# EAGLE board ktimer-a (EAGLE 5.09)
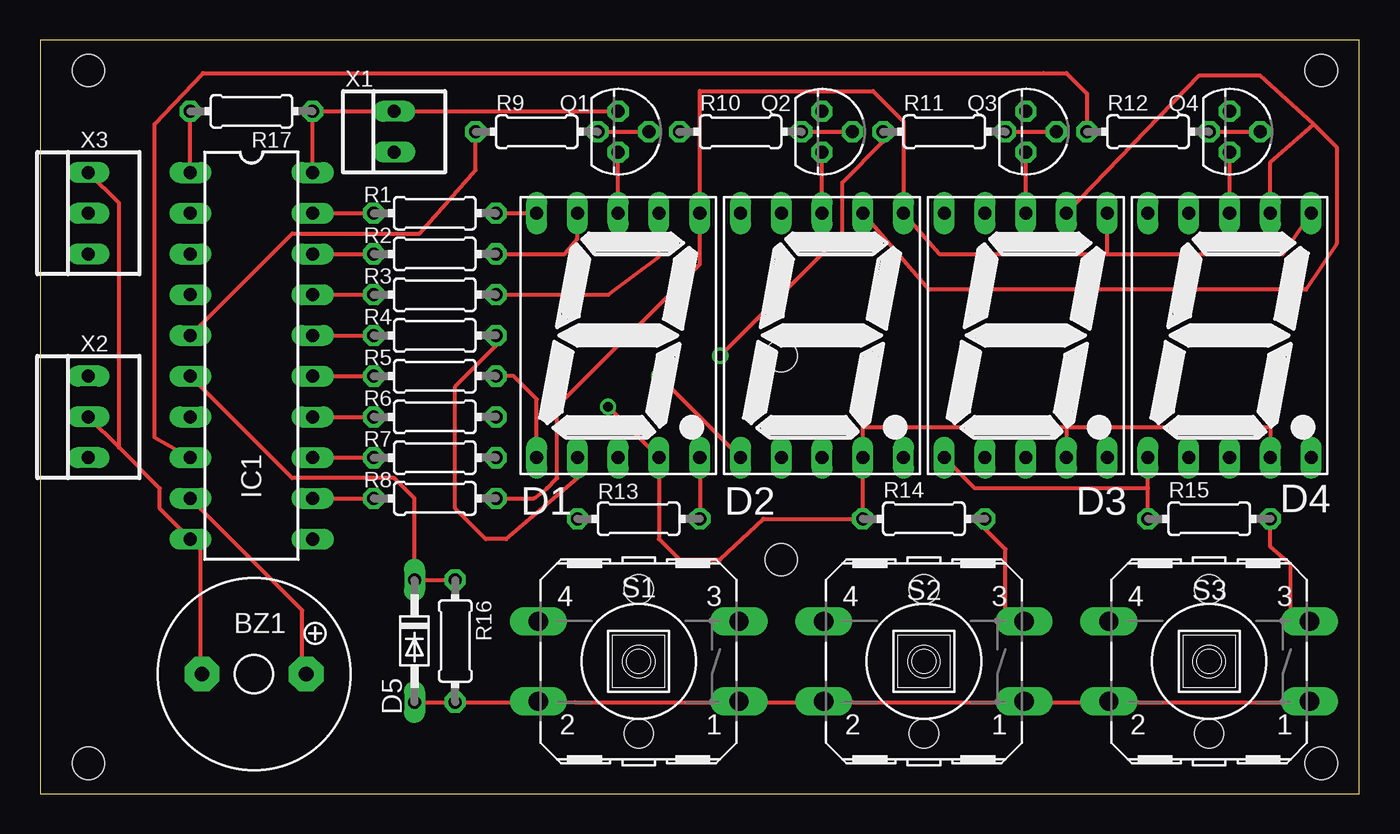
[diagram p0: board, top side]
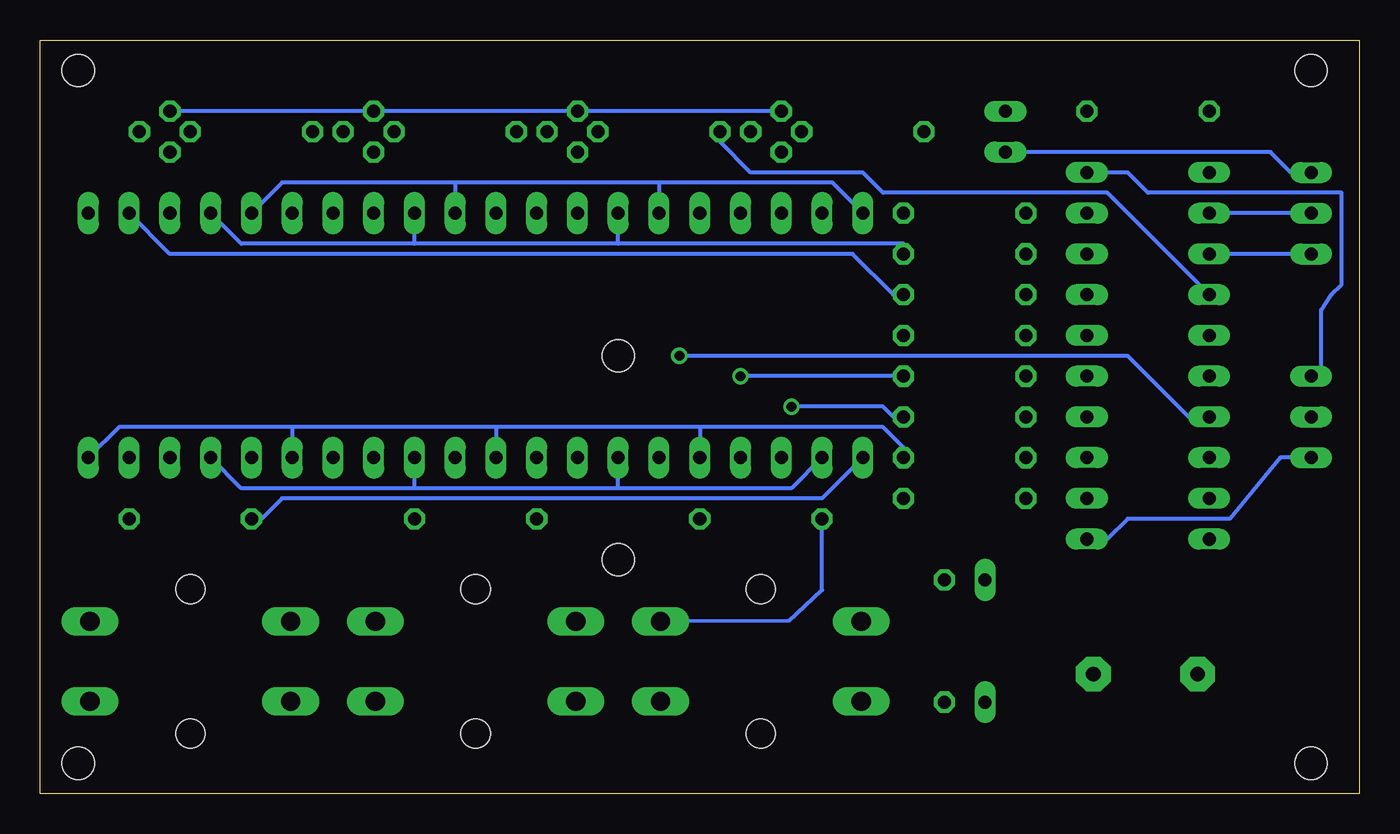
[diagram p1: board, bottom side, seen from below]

Size 82.22 x 46.98 mm. Coordinates in mm from the lower left corner, seen from the top.
Outline: 0,0 82.22,0 82.22,46.98 0,46.98 0,0
Copper layers (1*16): Top 0.035mm / dielectric 1.5mm / Bottom 0.035mm
Design rules "default": minimum track width 10mil, minimum drill 24mil, track to track 8mil, track to pad 8mil, pad to pad 8mil, via to via 8mil, smd to smd 8mil, copper to edge 40mil, drill to drill 8mil, minimum pad ring 10mil, minimum via ring 8mil, stop-mask expansion 4mil, vias tented up to drill 0mil, thermal gap 10mil
Holes 2 mm at 3.01,45.08 3.01,1.9 79.84,1.9 79.84,45.08 46.19,14.6 46.19,27.3

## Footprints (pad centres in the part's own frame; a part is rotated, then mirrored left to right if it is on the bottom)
F/QMBIII = drill 0.914 pad 2.159 octagon: + 3.251,0; - -3.251,0
7SEG-13 = drill 0.813 long: 1 -5.08,-7.62; 2 -2.54,-7.62; 3 0,-7.62; 4 2.54,-7.62; 5 5.08,-7.62; 6 5.08,7.62; 7 2.54,7.62; 8 0,7.62; 9 -2.54,7.62; 10 -5.08,7.62
DO34-7 = drill 0.813 long: A 3.81,0; C -3.81,0
DIL20 = drill 0.813 long: 1 -11.43,-3.81; 2 -8.89,-3.81; 3 -6.35,-3.81; 4 -3.81,-3.81; 5 -1.27,-3.81; 6 1.27,-3.81; 7 3.81,-3.81; 8 6.35,-3.81; 9 8.89,-3.81; 10 11.43,-3.81; 11 11.43,3.81; 12 8.89,3.81; 13 6.35,3.81; 14 3.81,3.81; 15 1.27,3.81; 16 -1.27,3.81; 17 -3.81,3.81; 18 -6.35,3.81; 19 -8.89,3.81; 20 -11.43,3.81
TO92 = drill 0.813 octagon: 1 1.27,0; 2 0,1.905; 3 -1.27,0
0204/7 = drill 0.813 octagon: 1 -3.81,0; 2 3.81,0
B3F-40XX = drill 1.194 long: 1 -6.248,2.489; 2 6.248,2.489; 3 -6.248,-2.489; 4 6.248,-2.489 | hole 1.803: 0,-4.496; 0,4.496
22-23-2021 = drill 0.813 long: 1 -1.27,0; 2 1.27,0
22-23-2031 = drill 0.813 long: 1 -2.54,0; 2 0,0; 3 2.54,0

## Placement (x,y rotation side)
BZ1  KC-1207  [F/QMBIII]  13.33,7.46 0 top
D1  [7SEG-13]  36.03,28.57 0 top
D2  [7SEG-13]  48.73,28.57 0 top
D3  [7SEG-13]  61.43,28.57 0 top
D4  [7SEG-13]  74.13,28.57 0 top
D5  1N4148  [DO34-7]  23.33,9.52 270 top
IC1  ATTINY2313-20PI  [DIL20]  13.17,27.3 270 top
Q1  BC557  [TO92]  36.03,41.27 270 top
Q2  BC557  [TO92]  48.73,41.27 270 top
Q3  BC557  [TO92]  61.43,41.27 270 top
Q4  BC557  [TO92]  74.13,41.27 270 top
R1  220R  [0204/7]  24.6,36.19 0 top
R2  220R  [0204/7]  24.6,33.65 0 top
R3  220R  [0204/7]  24.6,31.11 0 top
R4  220R  [0204/7]  24.6,28.57 0 top
R5  220R  [0204/7]  24.6,26.03 0 top
R6  220R  [0204/7]  24.6,23.49 0 top
R7  220R  [0204/7]  24.6,20.95 0 top
R8  220R  [0204/7]  24.6,18.41 0 top
R9  1k  [0204/7]  30.95,41.27 0 top
R10  1k  [0204/7]  43.65,41.27 0 top
R11  1k  [0204/7]  56.35,41.27 0 top
R12  1k  [0204/7]  69.05,41.27 0 top
R13  2k7  [0204/7]  37.3,17.14 180 top
R14  2k7  [0204/7]  55.08,17.14 0 top
R15  2k7  [0204/7]  72.86,17.14 0 top
R16  100k  [0204/7]  25.87,9.52 270 top
R17  10k  [0204/7]  13.17,42.54 180 top
S1  INC  [B3F-40XX]  37.3,8.25 180 top
S2  DEC  [B3F-40XX]  55.08,8.25 180 top
S3  START  [B3F-40XX]  72.86,8.25 180 top
X1  SUPPLY  [22-23-2021]  22.06,41.27 90 top
X2  XTRNL DEVICE  [22-23-2031]  3.01,23.49 90 top
X3  SERIAL  [22-23-2031]  3.01,36.19 90 top

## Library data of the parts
BZ1 = buzzer
D1-D4 = special
D5 = diode
IC1 = atmel2
Q1-Q4 = transistor-pnp
R1-R17 = rcl
S1-S3 = switch-omron
X1-X3 = con-molex

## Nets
+5V: IC1.20 Q1.3 Q2.3 Q3.3 Q4.3 R17.1 X1.2 X2.3
GND: BZ1.- IC1.10 X1.1 X2.2 X3.3
N$1: D1.10 D2.10 D3.10 D4.10 R1.2
N$2: D1.9 D2.9 D3.9 D4.9 R2.2
N$3: D1.7 D2.7 D3.7 D4.7 R3.2
N$4: D1.2 D2.2 D3.2 D4.2 R4.2
N$5: D1.1 D2.1 D3.1 D4.1 R5.2 R15.1
N$6: D1.4 D2.4 D3.4 D4.4 R6.2 R14.1
N$7: D1.5 D2.5 D3.5 D4.5 R7.2 R13.1
N$8: D1.6 D2.6 D3.6 D4.6 R8.2
N$9: IC1.19 R1.1
N$10: IC1.18 R2.1
N$11: IC1.17 R3.1
N$12: IC1.16 R4.1
N$13: IC1.15 R5.1
N$14: IC1.14 R6.1
N$15: IC1.13 R7.1
N$16: IC1.12 R8.1
N$17: Q1.2 R9.2
N$18: IC1.5 R9.1
N$19: D1.8 Q1.1
N$20: D2.8 Q2.1
N$21: D3.8 Q3.1
N$22: D4.3
N$23: Q2.2 R10.2
N$24: IC1.4 R10.1
N$25: Q3.2 R11.2
N$26: Q4.2 R12.2
N$27: IC1.7 R11.1
N$28: IC1.8 R12.1
N$29: IC1.1 R17.2
N$30: BZ1.+ IC1.9
N$31: R13.2 S1.3
N$32: R14.2 S2.3
N$33: R15.2 S3.3
N$34: D5.C IC1.6 R16.1
N$35: D5.A R16.2 S1.1 S1.2 S2.1 S2.2 S3.1 S3.2
N$36: D4.8 Q4.1
N$37: IC1.11 X2.1
N$38: IC1.3 X3.1
N$39: IC1.2 X3.2

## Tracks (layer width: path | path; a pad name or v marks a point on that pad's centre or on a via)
+5V
  Top 0.254: IC1.20 R17.1 X1.2 Q1.3
  Bottom 0.254: X2.3 2.38,26.66 2.38,30.16 1.74,31.11 1.11,31.74 1.11,37.46 13.17,37.46 14.44,38.73 IC1.20 | Q1.3 Q2.3 Q3.3 Q4.3
GND
  Top 0.254: 4.92,21.59 7.46,19.04 7.46,17.77 IC1.10 10,15.23 10,8.25 BZ1.- | 4.92,21.59 X2.2 | 4.92,21.59 4.92,36.83 X3.3
  Bottom 0.254: X3.3 4.28,38.73 5.55,40 X1.1
N$1
  Top 0.254: R1.2 D1.10
  Bottom 0.254: 43.65,38.09 56.35,38.09 | 43.65,38.09 D2.10 | 56.35,38.09 D3.10 | 56.35,38.09 67.14,38.09 D4.10 | 43.65,38.09 32.86,38.09 D1.10
N$2
  Top 0.254: R2.2 32.7,33.65 33.49,34.6 D1.9
  Bottom 0.254: 46.19,34.28 28.41,34.28 R2.2 | 46.19,34.28 D2.9 | 46.19,34.28 58.89,34.28 | 58.89,34.28 D3.9 | 58.89,34.28 69.69,34.28 D4.9
N$3
  Top 0.254: R3.2 35.39,31.11 38.57,33.49 D1.7 | 79.37,41.75 76.67,39.37 D4.7 | 79.37,41.75 80.8,40.32 80.8,34.28 78.89,31.43 55.4,31.43 D2.7 | 79.37,41.75 76.03,44.76 72.22,44.76 D3.7
  Bottom 0.254: R3.2 29.04,31.11 31.58,33.65 74.13,33.65 D4.7
N$4
  Top 0.254: R4.2 28.41,27.93 25.87,25.39 25.87,17.77 27.77,15.87 29.04,15.87 33.49,19.68 D1.2
  Bottom 0.254: 46.19,19.04 35.39,19.04 D1.2 | 46.19,19.04 D2.2 | 46.19,19.04 58.89,19.04 | 58.89,19.04 D3.2 | 58.89,19.04 69.69,19.04 D4.2
N$5  (via drill 0.61)
  Top 0.254: 69.05,19.04 58.25,19.04 D3.1 | 69.05,19.04 D4.1 | R15.1 69.05,19.04 | D1.1 30.95,24.6 29.52,26.03 R5.2 | v38.57,26.03 D2.1
  Bottom 0.254: R5.2 v38.57,26.03 | R15.1 68.41,17.14 67.14,18.41 33.49,18.41 D1.1
N$6  (via drill 0.61)
  Top 0.254: 63.97,22.86 76.67,22.86 D4.4 | v35.39,24.12 D1.4 38.57,15.87 39.84,14.6 42.38,14.6 45.08,17.14 R14.1 D2.4 51.27,22.86 63.97,22.86 | 63.97,22.86 D3.4
  Bottom 0.254: v35.39,24.12 29.68,24.12 29.04,23.49 R6.2
N$7
  Top 0.254: D1.5 R13.1
  Bottom 0.254: 41.11,22.86 29.68,22.86 28.41,21.59 R7.2 | 41.11,22.86 D1.5 | 41.11,22.86 53.81,22.86 | 53.81,22.86 D2.5 | 53.81,22.86 66.51,22.86 | 66.51,22.86 D3.5 | 66.51,22.86 77.3,22.86 D4.5
N$8
  Top 0.254: 66.51,33.65 56.03,33.65 D2.6 53.81,41.91 51.91,43.81 41.11,43.81 D1.6 41.11,33.02 32.22,24.12 32.22,19.68 31.58,19.04 30.79,18.41 R8.2 | 66.51,33.65 D3.6 | 66.51,33.65 77.46,33.65 D4.6
N$9
  Top 0.254: IC1.19 R1.1
N$10
  Top 0.254: IC1.18 R2.1
N$11
  Top 0.254: IC1.17 R3.1
N$12
  Top 0.254: IC1.16 R4.1
N$13
  Top 0.254: IC1.15 R5.1
N$14
  Top 0.254: IC1.14 R6.1
N$15
  Top 0.254: IC1.13 R7.1
N$16
  Top 0.254: IC1.12 R8.1
N$17
  Top 0.254: R9.2 Q1.2
N$18
  Top 0.254: IC1.5 15.71,34.92 23.65,34.92 27.14,38.89 R9.1
N$19
  Top 0.254: D1.8 Q1.1
N$20
  Top 0.254: D2.8 Q2.1
N$21
  Top 0.254: D3.8 Q3.1
N$23
  Top 0.254: R10.2 Q2.2
N$24
  Bottom 0.254: IC1.4 15.71,37.46 29.68,37.46 30.95,38.73 37.94,38.73 39.84,40.63 R10.1
N$25
  Top 0.254: R11.2 Q3.2
N$26
  Top 0.254: R12.2 Q4.2
N$27  (via drill 0.61)
  Top 0.254: v42.38,27.3 50,34.92 50,38.09 52.54,40.63 R11.1
  Bottom 0.254: v42.38,27.3 14.44,27.3 10.63,23.49 IC1.7
N$28
  Top 0.254: IC1.8 7.14,22.22 7.14,41.75 10.15,44.92 62.54,44.92 63.97,44.92 65.24,43.65 R12.1
N$29
  Top 0.254: IC1.1 R17.2
N$30
  Top 0.254: IC1.9 16.34,11.42 16.34,8.25 BZ1.+
N$31
  Bottom 0.254: R13.2 33.49,12.7 35.55,10.79 S1.3
N$32
  Top 0.254: R14.2 58.89,16.5 60.16,15.23 60.16,11.42 S2.3
N$33
  Top 0.254: R15.2 76.67,15.39 77.94,14.28 77.94,11.42 S3.3
N$34
  Top 0.254: R16.1 D5.C 23.33,18.41 22.06,19.68 15.71,19.68 IC1.6
N$35
  Top 0.254: S3.1 77.78,5.71 68.41,5.71 S3.2 65.24,5.71 62.7,5.71 S2.1 60.16,5.71 50.64,5.71 S2.2 47.46,5.71 44.92,5.71 S1.1 42.22,5.71 33.33,5.71 S1.2 29.68,5.71 R16.2 D5.A
N$36
  Top 0.254: D4.8 Q4.1
N$37
  Bottom 0.254: X2.1 4.92,20.95 8.09,17.14 14.44,17.14 15.71,15.87 IC1.11
N$38
  Bottom 0.254: X3.1 IC1.3
N$39
  Bottom 0.254: X3.2 IC1.2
